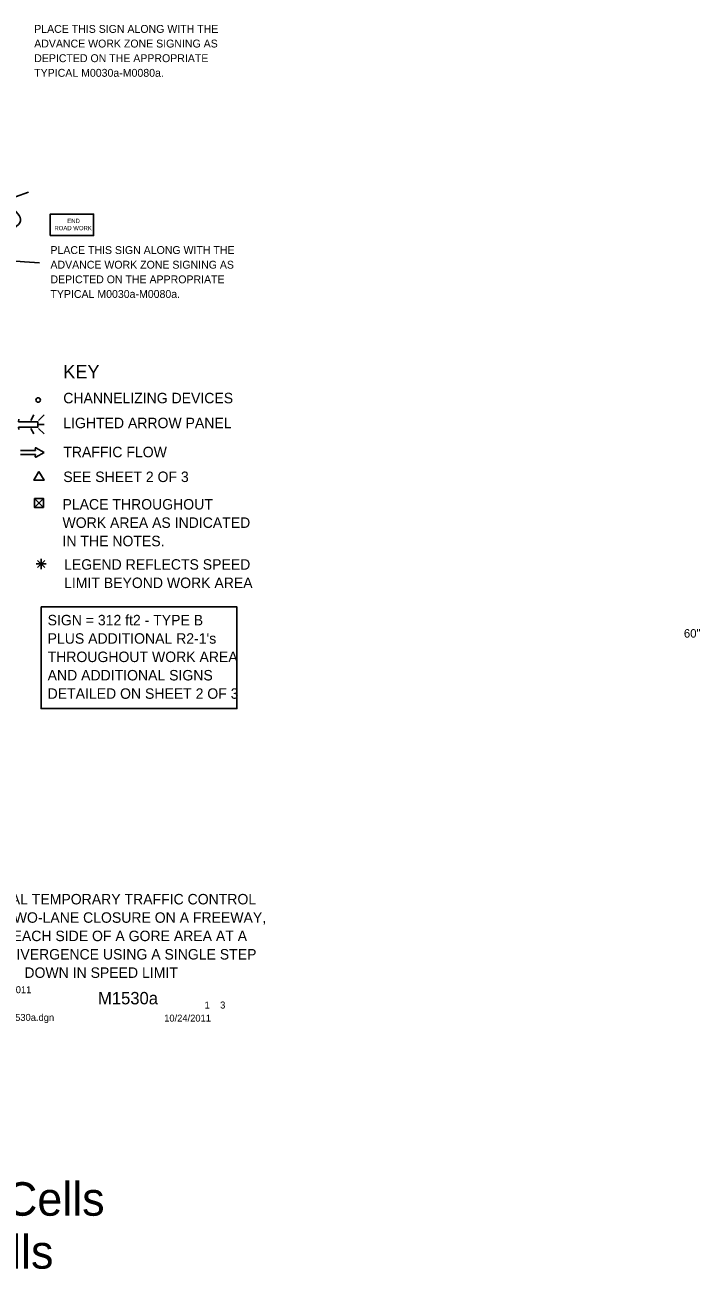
# Model space of a CAD drawing. Extents: x 16452 to 19508, y 5713 to 7079.
# Drawn here: x 17224 to 17823, y 5713 to 6818 of the extents above; entities that cross this region are included whole.
import ezdxf

# ---------------------------------------------------------------- set-up
doc = ezdxf.new("R2010")
doc.units = 0
for name, color, linetype in [('BORDER', 7, 'Continuous'), ('BORDER_SIGNAL_WO', 7, 'Continuous'), ('MT_SCRATCH_LEVEL_E', 7, 'Continuous'), ('PAVT_EDGE_EX', 7, 'Continuous'), ('TRAFFIC_SIGNS_PR', 7, 'Continuous'), ('TYPICAL_TEXT_DIMEN_EX', 7, 'Continuous'), ('TYPICAL_TEXT_DIMEN_PR', 7, 'Continuous')]:
    doc.layers.add(name, color=color, linetype=linetype)

msp = doc.modelspace()

# ---------------------------------------------------------------- linework, layer by layer
at = {"layer": 'MT_SCRATCH_LEVEL_E'}
for p, q in [((17233.7, 6440.1), (17220.5, 6440.1)), ((17233.4, 6441.9), (17233.7, 6440.1)), ((17241.3, 6438.3), (17234.1, 6442.4)), ((17220.5, 6436.4), (17233.7, 6436.4)), ((17233.7, 6436.4), (17233.4, 6434.6)), ((17234.1, 6434.1), (17241.3, 6438.3))]:
    msp.add_line(p, q, dxfattribs=at)
for centre, start, end in [((17233.9, 6442), 60.4248, 189.9638), ((17233.9, 6434.5), 170.0362, 299.7731)]:
    msp.add_arc(centre, 0.463, start, end, dxfattribs=at)
at = {"layer": 'PAVT_EDGE_EX'}
msp.add_arc((17319.9, 6383.8), 300, 107.923, 180, dxfattribs=at)
at = {"layer": 'TRAFFIC_SIGNS_PR'}
for p, q in [((17229.5, 6466.7), (17232.3, 6471.6)), ((17236.4, 6466.7), (17241.3, 6471.6)), ((17236.4, 6463.2), (17241.3, 6463.2)), ((17232.4, 6454.7), (17229.5, 6459.6)), ((17236.4, 6459.6), (17241.3, 6454.7))]:
    msp.add_line(p, q, dxfattribs=at)
msp.add_lwpolyline([(17246.9, 6630.7), (17285.3, 6630.7), (17285.3, 6649.9), (17246.9, 6649.9)], close=True, dxfattribs=at)
msp.add_lwpolyline([(17219.1, 6458.5), (17218.7, 6460.7), (17235.7, 6460.7), (17235.7, 6465.5), (17218.7, 6465.5), (17219.1, 6467.8)], dxfattribs=at)
msp.add_circle((17236.1, 6484.8), 2, dxfattribs=at)
at = {"layer": 'TYPICAL_TEXT_DIMEN_EX'}
msp.add_lwpolyline([(17238.7, 6301.2), (17412.4, 6301.2), (17412.4, 6210.9), (17238.7, 6210.9)], close=True, dxfattribs=at)
at = {"layer": 'TYPICAL_TEXT_DIMEN_PR'}
for p, q in [((17232.8, 6397.5), (17240.8, 6389.5)), ((17232.8, 6389.5), (17240.8, 6397.5)), ((17238.7, 6339.3), (17234.2, 6339.3)), ((17235.5, 6342.5), (17241.9, 6336.1)), ((17241.9, 6342.5), (17235.5, 6336.1)), ((17238.7, 6339.3), (17238.7, 6343.7)), ((17238.7, 6339.3), (17241.9, 6339.3)), ((17238.7, 6339.3), (17243.2, 6339.3)), ((17238.7, 6339.3), (17238.7, 6334.8))]:
    msp.add_line(p, q, dxfattribs=at)
for points in [[(17236.8, 6421.5), (17232.3, 6413.6), (17241.4, 6413.6)], [(17232.8, 6397.5), (17232.8, 6389.5), (17240.8, 6389.5), (17240.8, 6397.5)]]:
    msp.add_lwpolyline(points, close=True, dxfattribs=at)
msp.add_open_spline([(17211.5, 6657), (17216.4, 6652.5), (17226.4, 6643.1), (17205.5, 6632.6), (17175.7, 6610.9), (17212.4, 6608.3), (17237.4, 6606.6)], degree=3, dxfattribs=at)

# ---------------------------------------------------------------- texts
at = {"layer": 'BORDER'}
for s, p in [('TYPICAL TEMPORARY TRAFFIC CONTROL', (17175.2, 6037.1)), ('FOR A TWO-LANE CLOSURE ON A FREEWAY,', (17165.4, 6020.8)), ('ONE ON EACH SIDE OF A GORE AREA AT A ', (17160.9, 6004.5)), ('MAJOR DIVERGENCE USING A SINGLE STEP ', (17160.9, 5988.2)), ('DOWN IN SPEED LIMIT', (17223.9, 5971.9))]:
    msp.add_text(s, height=9.3, dxfattribs=at).set_placement(p)
at = {"layer": 'BORDER_SIGNAL_WO'}
for s, height, p in [('    OCTOBER 2011    ', 6.2, (17159.1, 5958.3)), ('    M1530a   ', 11, (17272.9, 5948.4)), (' 1    3 ', 6.2, (17381.4, 5944.7)), ('PW RD/TS/Typicals/Signs/MT FWY/M1530a.dgn      ', 6.2, (17070.6, 5933.7)), ('10/24/2011    ', 6.2, (17347.9, 5933.1)), ('AS = 0.8 for Sign Cells', 29.727, (16894, 5760.8)), ('     1.0 for Text Cells', 29.727, (16894, 5713.8))]:
    msp.add_text(s, height=height, dxfattribs=at).set_placement(p)
at = {"layer": 'TRAFFIC_SIGNS_PR'}
for s, height, p in [('PLACE THIS SIGN ALONG WITH THE', 7, (17232.6, 6810.7)), ('ADVANCE WORK ZONE SIGNING AS', 7, (17232.6, 6797.7)), ('DEPICTED ON THE APPROPRIATE', 7, (17232.6, 6784.7)), ('TYPICAL M0030a-M0080a.', 7, (17232.6, 6771.7)), ('ROAD WORK', 3.83, (17250.5, 6635.5)), ('END', 3.83, (17261.9, 6641.9)), ('PLACE THIS SIGN ALONG WITH THE', 7, (17247, 6614.4)), ('ADVANCE WORK ZONE SIGNING AS', 7, (17247, 6601.4)), ('DEPICTED ON THE APPROPRIATE', 7, (17247, 6588.4)), ('TYPICAL M0030a-M0080a.', 7, (17247, 6575.4))]:
    msp.add_text(s, height=height, dxfattribs=at).set_placement(p)
at = {"layer": 'TYPICAL_TEXT_DIMEN_EX'}
for s, height, p in [('KEY', 12, (17258.4, 6503.9)), ('CHANNELIZING DEVICES', 9.3, (17258.4, 6481.9)), ('LIGHTED ARROW PANEL', 9.3, (17258.4, 6459.8)), ('TRAFFIC FLOW', 9.3, (17258.4, 6434)), ('SEE SHEET 2 OF 3', 9.3, (17258.4, 6412)), ('PLACE THROUGHOUT', 9.3, (17257.7, 6387.6)), ('WORK AREA AS INDICATED', 9.3, (17257.7, 6371.3)), ('IN THE NOTES.', 9.3, (17257.7, 6355)), ('LEGEND REFLECTS SPEED', 9.3, (17259.1, 6334.2)), ('LIMIT BEYOND WORK AREA', 9.3, (17259.1, 6317.9)), ('SIGN = 312 ft2 - TYPE B', 9.3, (17244.5, 6284.8)), ("PLUS ADDITIONAL R2-1's", 9.3, (17244.5, 6268.5)), ('THROUGHOUT WORK AREA', 9.3, (17244.5, 6252.2)), ('AND ADDITIONAL SIGNS', 9.3, (17244.5, 6235.9)), ('DETAILED ON SHEET 2 OF 3', 9.3, (17244.5, 6219.6))]:
    msp.add_text(s, height=height, dxfattribs=at).set_placement(p)
at = {"layer": 'TYPICAL_TEXT_DIMEN_PR'}
msp.add_text('60"', height=7.55, dxfattribs=at).set_placement((17808.9, 6273.9))

doc.saveas('drawing.dxf')
